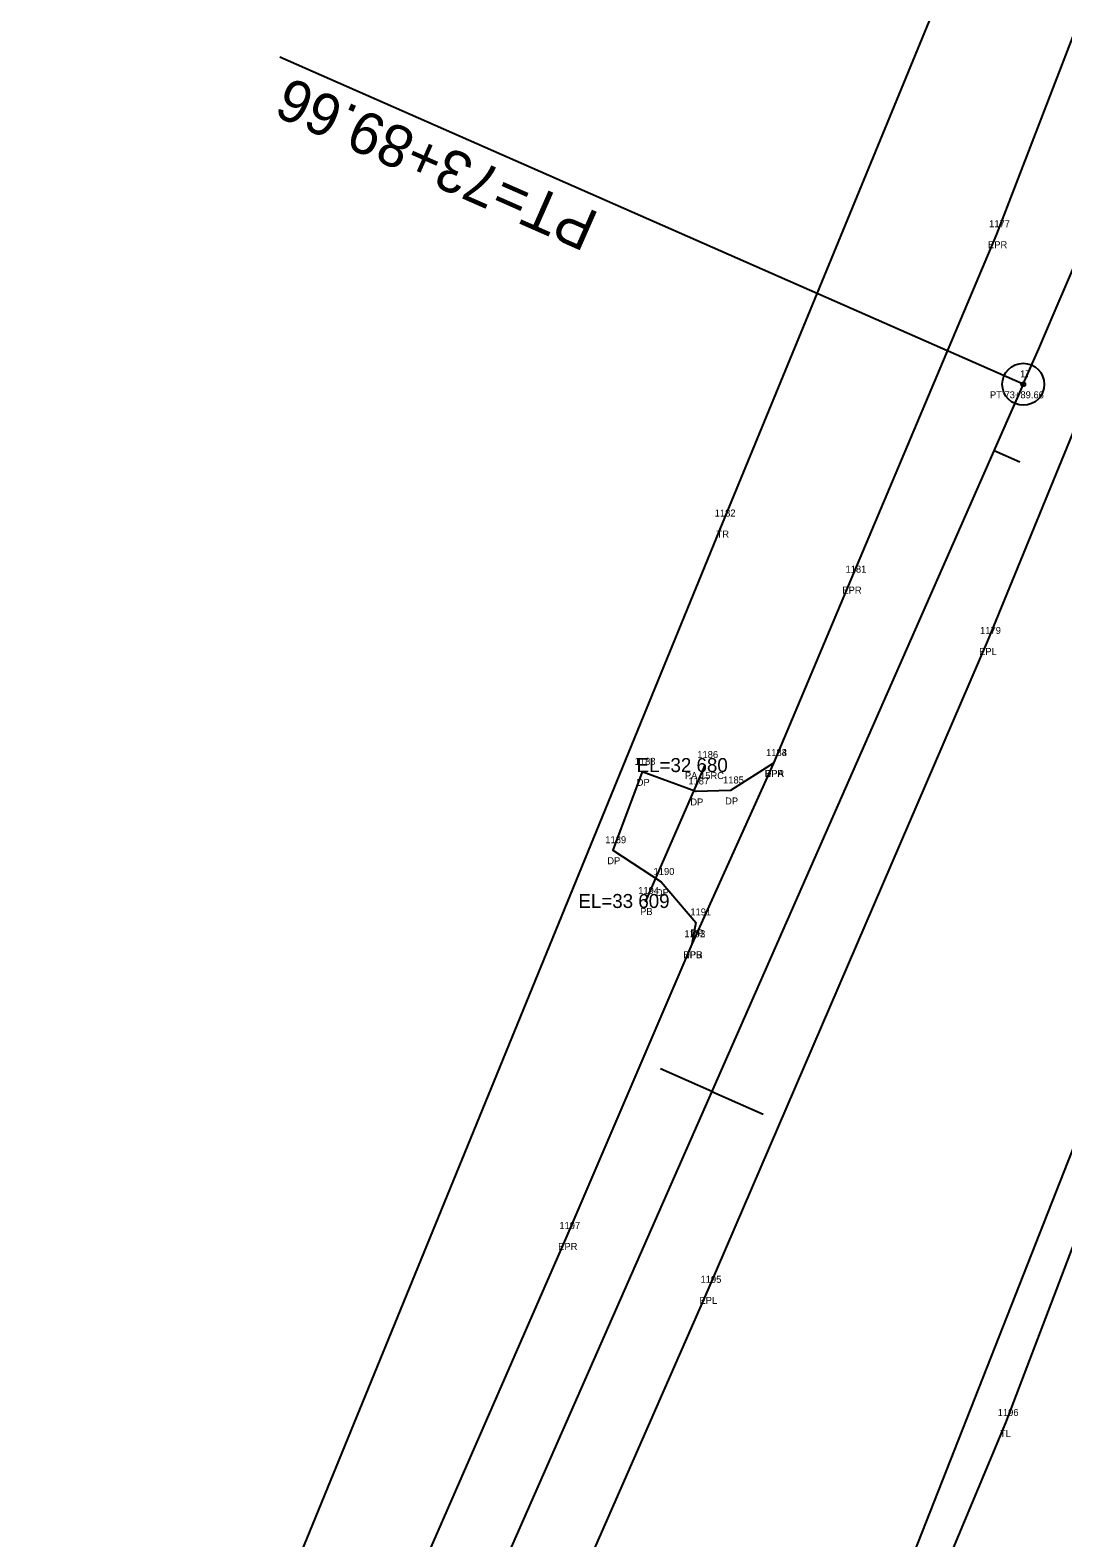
# Model space of a CAD drawing. Extents: x 2432632 to 2433497, y 684847 to 688233.
# Drawn here: x 2432851.9 to 2432999.3, y 685310.2 to 685525.5 of the extents above; entities that cross this region are included whole.
import ezdxf

# ---------------------------------------------------------------- set-up
doc = ezdxf.new("R2010")
doc.units = 0
for name, color, linetype in [('RD_EX_DR_Pipe', 7, 'Continuous'), ('RD_EX_DR_Pipe_txCode', 7, 'Continuous'), ('RD_EX_Driveway', 7, 'Continuous'), ('RD_EX_Driveway_txCode', 7, 'Continuous'), ('RD_EX_Fence_Other', 7, 'Continuous'), ('RD_EX_Road', 7, 'Continuous'), ('RD_EX_Road_txCode', 7, 'Continuous'), ('RD_EX_VEG', 7, 'Continuous'), ('RD_EX_VEG_txCode', 7, 'Continuous'), ('RD_HC_Cl', 7, 'Continuous'), ('RD_HC_Data', 7, 'Continuous'), ('RD_HC_Data_Tic', 7, 'Continuous'), ('RD_HC_txCode', 7, 'Continuous'), ('RD_SMD_Locator', 7, 'Continuous'), ('RD_TX_Pipe_ElevEX', 7, 'Continuous')]:
    doc.layers.add(name, color=color, linetype=linetype)

msp = doc.modelspace()

# ---------------------------------------------------------------- linework, layer by layer
at = {"layer": 'RD_EX_DR_Pipe'}
msp.add_line((2432948.19, 685420.55), (2432939.72, 685401.14), dxfattribs=at)
at = {"layer": 'RD_EX_Driveway'}
msp.add_lwpolyline([(2432957.98, 685420.84), (2432951.85, 685416.92), (2432946.88, 685416.78), (2432939.23, 685419.58), (2432935.03, 685408.39), (2432941.96, 685403.86), (2432946.89, 685398.08), (2432946.33, 685394.97)], dxfattribs=at)
at = {"layer": 'RD_EX_Fence_Other'}
msp.add_lwpolyline([(2433123.26, 685650.94), (2433063.8, 685520.15), (2433021.44, 685418.51), (2432949, 685234.28), (2432929.52, 685179.08)], dxfattribs=at)
at = {"layer": 'RD_EX_Road'}
for points in [[(2433057.55, 685694.23), (2433042.27, 685641.38), (2433024.96, 685589.31), (2433008.78, 685545.65), (2432989.83, 685496.35), (2432969.04, 685447.03), (2432957.98, 685420.84), (2432946.33, 685394.97), (2432928.47, 685353.31), (2432900.81, 685290.04), (2432890.58, 685267.74), (2432865.39, 685209.09), (2432858.68, 685194.25), (2432808.1, 685079.72), (2432767.11, 684987)], [(2433077.66, 685687.92), (2433062.23, 685635.7), (2433044.84, 685582.68), (2433028.22, 685537.07), (2433009.68, 685489.83), (2432988.53, 685438.27), (2432948.62, 685345.62), (2432907.86, 685252.74), (2432887.37, 685205.96), (2432872.08, 685170.45), (2432827.85, 685071.69), (2432787.31, 684979.59)]]:
    msp.add_lwpolyline(points, dxfattribs=at)
at = {"layer": 'RD_EX_VEG'}
for points in [[(2433137.8, 685665.13), (2433067, 685525.91), (2432991.08, 685326.61), (2432934.15, 685190.44)], [(2433025.22, 685647.63), (2432992.1, 685555.75), (2432950.65, 685455.04), (2432854.18, 685219.34)]]:
    msp.add_lwpolyline(points, dxfattribs=at)
at = {"layer": 'RD_HC_Cl'}
msp.add_line((2432993.64, 685474.92), (2432777.18, 684983.39), dxfattribs=at)
msp.add_arc((2431682.72, 686052.2), 1432.39, 336.23293, 350.43349, dxfattribs=at)
at = {"layer": 'RD_HC_Data'}
msp.add_line((2432993.64, 685474.92), (2432887.51, 685521.65), dxfattribs=at)
for radius in [3, 0.282]:
    msp.add_circle((2432993.64, 685474.92), radius, dxfattribs=at)
at = {"layer": 'RD_HC_Data_Tic'}
for p, q in [((2432989.47, 685465.45), (2432993.13, 685463.84)), ((2432949.16, 685373.93), (2432941.84, 685377.16)), ((2432949.16, 685373.93), (2432956.49, 685370.71))]:
    msp.add_line(p, q, dxfattribs=at)
at = {"layer": 'RD_SMD_Locator'}
for centre in [(2432989.83, 685496.35), (2432993.64, 685474.92), (2432950.65, 685455.04), (2432969.04, 685447.03), (2432988.53, 685438.27), (2432939.23, 685419.58), (2432948.19, 685420.55), (2432957.98, 685420.84), (2432957.98, 685420.84), (2432946.88, 685416.78), (2432951.85, 685416.92), (2432935.03, 685408.39), (2432941.96, 685403.86), (2432939.72, 685401.14), (2432946.89, 685398.08), (2432946.33, 685394.97), (2432946.33, 685394.97), (2432928.47, 685353.31), (2432948.62, 685345.62), (2432991.08, 685326.61)]:
    msp.add_circle(centre, 0.001, dxfattribs=at)

# ---------------------------------------------------------------- texts
at = {"layer": 'RD_EX_DR_Pipe_txCode'}
for s, p in [('1186', (2432947.1, 685421.55)), ('PA 15RC', (2432945.34, 685418.55)), ('1194', (2432938.66, 685402.14)), ('PB', (2432938.94, 685399.14))]:
    msp.add_text(s, height=1, dxfattribs=at).set_placement(p)
at = {"layer": 'RD_EX_Driveway_txCode'}
for s, p in [('1188', (2432938.16, 685420.58)), ('1184', (2432956.92, 685421.84)), ('DPA', (2432956.71, 685418.84)), ('DP', (2432938.45, 685417.58)), ('1187', (2432945.82, 685417.78)), ('1185', (2432950.78, 685417.92)), ('DP', (2432946.1, 685414.78)), ('DP', (2432951.07, 685414.92)), ('1189', (2432933.97, 685409.39)), ('DP', (2432934.25, 685406.39)), ('1190', (2432940.86, 685404.86)), ('DP', (2432941.18, 685401.86)), ('1191', (2432946.11, 685399.08)), ('1192', (2432945.26, 685395.97)), ('DP', (2432946.11, 685396.08)), ('DPB', (2432945.08, 685392.97))]:
    msp.add_text(s, height=1, dxfattribs=at).set_placement(p)
at = {"layer": 'RD_EX_Road_txCode'}
for s, p in [('1177', (2432988.76, 685497.35)), ('EPR', (2432988.6, 685494.35)), ('1181', (2432968.26, 685448.03)), ('EPR', (2432967.81, 685445.03)), ('1179', (2432987.47, 685439.27)), ('EPL', (2432987.33, 685436.27)), ('1183', (2432956.92, 685421.84)), ('EPR', (2432956.75, 685418.84)), ('1193', (2432945.26, 685395.97)), ('EPR', (2432945.1, 685392.97)), ('1197', (2432927.41, 685354.31)), ('EPR', (2432927.24, 685351.31)), ('1195', (2432947.56, 685346.62)), ('EPL', (2432947.41, 685343.62))]:
    msp.add_text(s, height=1, dxfattribs=at).set_placement(p)
at = {"layer": 'RD_EX_VEG_txCode'}
for s, p in [('1182', (2432949.59, 685456.04)), ('TR', (2432949.85, 685453.04)), ('1196', (2432989.99, 685327.61)), ('TL', (2432990.31, 685324.61))]:
    msp.add_text(s, height=1, dxfattribs=at).set_placement(p)
at = {"layer": 'RD_HC_Data'}
msp.add_text('PT=73+89.66', height=6, rotation=156.2329, dxfattribs=at).set_placement((2432933.34, 685499.29))
at = {"layer": 'RD_HC_txCode'}
for s, p in [('17', (2432993.19, 685475.92)), ('PT 73+89.66', (2432988.88, 685472.92))]:
    msp.add_text(s, height=1, dxfattribs=at).set_placement(p)
at = {"layer": 'RD_TX_Pipe_ElevEX'}
for s, p in [('EL=32 680  ', (2432938.44, 685419.55)), ('EL=33 609  ', (2432930.13, 685400.14))]:
    msp.add_text(s, height=2, dxfattribs=at).set_placement(p)

doc.saveas('drawing.dxf')
